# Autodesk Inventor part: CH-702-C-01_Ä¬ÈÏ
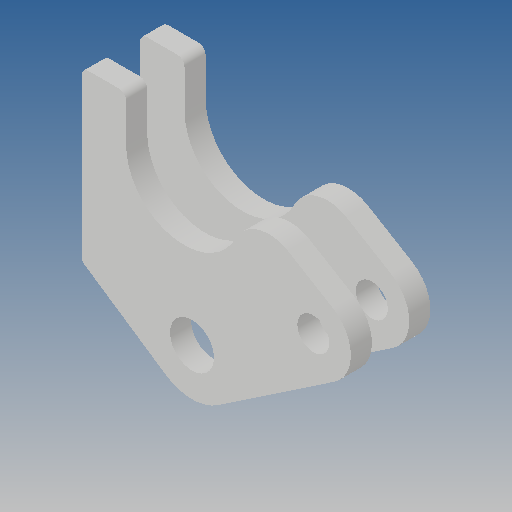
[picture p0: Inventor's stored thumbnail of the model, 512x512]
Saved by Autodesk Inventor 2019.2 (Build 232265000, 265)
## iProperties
Created: 2010-06
Part Number: CH-702-C-01_Ä¬ÈÏ
Material: Ogólny
Document SubType Name: Modeling
Designer: CADENGINEERING4
Density: 1 g/cm^3
Appearance: Domyślna
Author: CADENGINEERING4
Revision Number: ÈÎºÎ
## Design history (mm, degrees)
feature "NONE"
feature "NONE:1"
node "Bryła1"
node "Bryła2"
